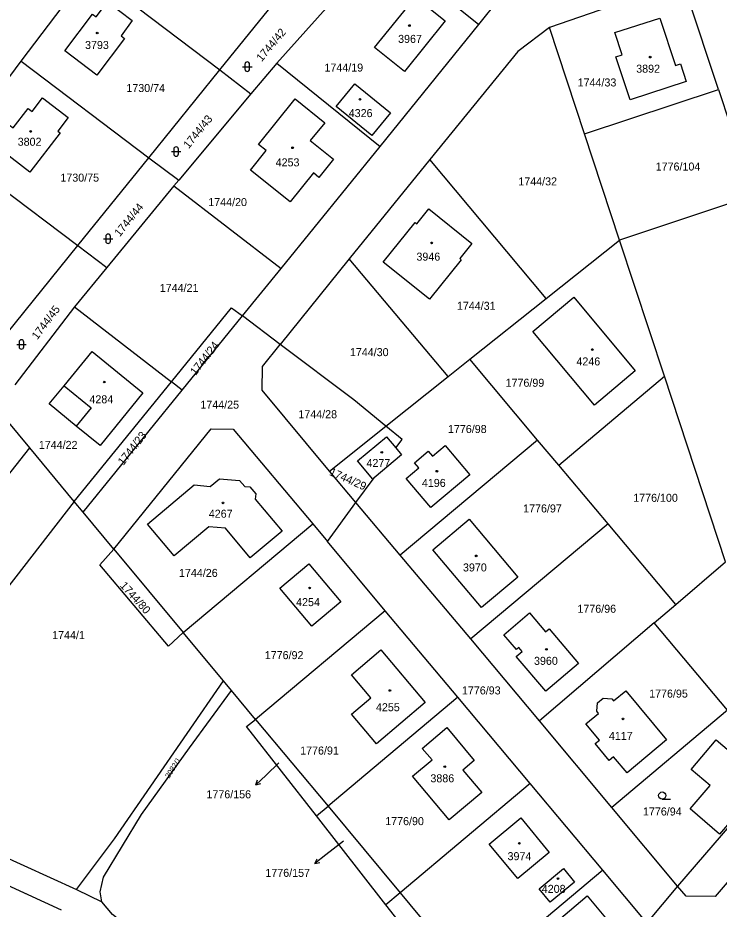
# Model space of a CAD drawing. Extents: x -679220 to -673243, y -1075091 to -1066557.
# Drawn here: x -677014 to -676865, y -1072590.3 to -1072401 of the extents above; entities that cross this region are included whole.
import ezdxf

# ---------------------------------------------------------------- set-up
doc = ezdxf.new("R2010")
doc.units = 0
for name, color, linetype in [('Hranice parcel', 7, 'Continuous'), ('Parcelní čísla', 7, 'Continuous'), ('Pop  PČ popisy', 7, 'Continuous'), ('Vnitřní kresba', 7, 'Continuous'), ('Značky budov', 7, 'Continuous'), ('Značky kultur', 7, 'Continuous')]:
    doc.layers.add(name, color=color, linetype=linetype)

msp = doc.modelspace()

# ---------------------------------------------------------------- linework, layer by layer
at = {"layer": 'Hranice parcel'}
for p, q in [((-676936.55, -1072385.82), (-676916.03, -1072402.47)), ((-677013.21, -1072410.27), (-676998.74, -1072391.12)), ((-676998.74, -1072391.12), (-676971, -1072412.08)), ((-676971, -1072412.08), (-676955.89, -1072393.41)), ((-676948.47, -1072399.01), (-676958.94, -1072410.64)), ((-676936.98, -1072428.37), (-676916.03, -1072402.47)), ((-676893.58, -1072425.69), (-676901.03, -1072403.13)), ((-677027.68, -1072429.42), (-677013.21, -1072410.27)), ((-677013.21, -1072410.27), (-676986.1, -1072430.75)), ((-676986.1, -1072430.75), (-676971, -1072412.08)), ((-676971, -1072412.08), (-676964.44, -1072417.17)), ((-676958.94, -1072410.64), (-676964.44, -1072417.17)), ((-676958.94, -1072410.64), (-676936.98, -1072428.37)), ((-676964.44, -1072417.17), (-676979.76, -1072435.5)), ((-676893.58, -1072425.69), (-676865.11, -1072416.25)), ((-676886.14, -1072448.25), (-676893.58, -1072425.69)), ((-676958.03, -1072454.3), (-676936.98, -1072428.37)), ((-677027.68, -1072429.42), (-677001.2, -1072449.42)), ((-677001.2, -1072449.42), (-676986.1, -1072430.75)), ((-676986.1, -1072430.75), (-676979.76, -1072435.5)), ((-676926.44, -1072431.16), (-676943.53, -1072452.25)), ((-676901.74, -1072460.64), (-676926.44, -1072431.16)), ((-676980.82, -1072436.75), (-676995.05, -1072454.05)), ((-676979.76, -1072435.5), (-676980.82, -1072436.75)), ((-676980.82, -1072436.75), (-676958.03, -1072454.3)), ((-676901.74, -1072460.64), (-676886.14, -1072448.25)), ((-676876.54, -1072477.15), (-676886.14, -1072448.25)), ((-677019.83, -1072472.45), (-677001.2, -1072449.42)), ((-677001.2, -1072449.42), (-676995.05, -1072454.05)), ((-676943.53, -1072452.25), (-676958.19, -1072470.4)), ((-676922.55, -1072477.22), (-676943.53, -1072452.25)), ((-676995.05, -1072454.05), (-677001.89, -1072462.45)), ((-676966.23, -1072464.36), (-676958.03, -1072454.3)), ((-676917.9, -1072473.51), (-676901.74, -1072460.64)), ((-677001.89, -1072462.45), (-677014.57, -1072478.97)), ((-677001.89, -1072462.45), (-676981.32, -1072478.34)), ((-676979.04, -1072480.1), (-676966.23, -1072464.36)), ((-676958.19, -1072470.4), (-676966.23, -1072464.36)), ((-676961.96, -1072475.06), (-676958.19, -1072470.4)), ((-676922.55, -1072477.22), (-676917.9, -1072473.51)), ((-676903.54, -1072490.7), (-676917.9, -1072473.51)), ((-677001.95, -1072503.72), (-676981.32, -1072478.34)), ((-676979.04, -1072480.1), (-676981.32, -1072478.34)), ((-676935.75, -1072487.75), (-676922.55, -1072477.22)), ((-676899.03, -1072496.01), (-676876.54, -1072477.15)), ((-676863.58, -1072516.59), (-676876.54, -1072477.15)), ((-677000.06, -1072506), (-676979.04, -1072480.1)), ((-677011.4, -1072492.35), (-677018.39, -1072483.95)), ((-676947.74, -1072497.31), (-676935.75, -1072487.75)), ((-676935.65, -1072490), (-676933.63, -1072492.39)), ((-676903.54, -1072490.7), (-676932.73, -1072515.13)), ((-676899.03, -1072496.01), (-676903.54, -1072490.7)), ((-677063.46, -1072557.99), (-677011.4, -1072492.35)), ((-677001.95, -1072503.72), (-677011.4, -1072492.35)), ((-676942.11, -1072504), (-676947.74, -1072497.31)), ((-676888.56, -1072508.51), (-676899.03, -1072496.01)), ((-676942.11, -1072504), (-676938.28, -1072498.75)), ((-676938.28, -1072498.75), (-676938.55, -1072498.98)), ((-677001.95, -1072503.72), (-677049.16, -1072564.49)), ((-677000.06, -1072506), (-677001.95, -1072503.72)), ((-676948.16, -1072512.28), (-676942.11, -1072504)), ((-676932.73, -1072515.13), (-676942.11, -1072504)), ((-676993.55, -1072513.87), (-677000.06, -1072506)), ((-676978.83, -1072531.58), (-676951.31, -1072508.5)), ((-676951.31, -1072508.5), (-676948.16, -1072512.28)), ((-676888.56, -1072508.51), (-676917.69, -1072532.9)), ((-676874.19, -1072525.66), (-676888.56, -1072508.51)), ((-676935.94, -1072526.95), (-676948.16, -1072512.28)), ((-676993.55, -1072513.87), (-676978.83, -1072531.58)), ((-676917.69, -1072532.9), (-676932.73, -1072515.13)), ((-676874.19, -1072525.66), (-676863.58, -1072516.59)), ((-676878.76, -1072529.49), (-676874.19, -1072525.66)), ((-676935.94, -1072526.95), (-676963.45, -1072550.02)), ((-676920.45, -1072545.27), (-676935.94, -1072526.95)), ((-676878.76, -1072529.49), (-676903.14, -1072550.36)), ((-676863.18, -1072548.07), (-676878.76, -1072529.49)), ((-676970.29, -1072541.82), (-676978.83, -1072531.58)), ((-676903.14, -1072550.36), (-676917.69, -1072532.9)), ((-676968.55, -1072543.9), (-676970.29, -1072541.82)), ((-676963.45, -1072550.02), (-676968.55, -1072543.9)), ((-676920.45, -1072545.27), (-676948.01, -1072568.43)), ((-676905.1, -1072563.63), (-676920.45, -1072545.27)), ((-676863.18, -1072548.07), (-676887.79, -1072568.76)), ((-676965.38, -1072551.53), (-676963.45, -1072550.02)), ((-676963.45, -1072550.02), (-676948.01, -1072568.43)), ((-676887.79, -1072568.76), (-676903.14, -1072550.36)), ((-676950.51, -1072570.53), (-676965.38, -1072551.53)), ((-676905.1, -1072563.63), (-676932.72, -1072586.85)), ((-676889.67, -1072582.03), (-676905.1, -1072563.63)), ((-677049.16, -1072564.49), (-677001.46, -1072586.15)), ((-676950.51, -1072570.53), (-676948.01, -1072568.43)), ((-676948.01, -1072568.43), (-676932.72, -1072586.85)), ((-676873.78, -1072585.43), (-676887.79, -1072568.76)), ((-676859.53, -1072568.86), (-676873.78, -1072585.43)), ((-676935.74, -1072589.39), (-676950.51, -1072570.53)), ((-676889.67, -1072582.03), (-676917.41, -1072605.32)), ((-676880.3, -1072593.22), (-676889.67, -1072582.03)), ((-677001.46, -1072586.15), (-676996.12, -1072588.79)), ((-676873.78, -1072585.43), (-676880.3, -1072593.22)), ((-676932.72, -1072586.85), (-676935.74, -1072589.39)), ((-676932.72, -1072586.85), (-676917.41, -1072605.32)), ((-676899.11, -1072592.68), (-676893, -1072587.47)), ((-676893, -1072587.47), (-676884.26, -1072597.96)), ((-676920.96, -1072608.27), (-676935.74, -1072589.39))]:
    msp.add_line(p, q, dxfattribs=at)
for points in [[(-676916.03, -1072402.47), (-676911.66, -1072396.99), (-676907.56, -1072394.23), (-676891.76, -1072389.1)], [(-676865.11, -1072416.25), (-676871.72, -1072396.17), (-676875.51, -1072394.24), (-676901.03, -1072403.13)], [(-676923.13, -1072401.7), (-676931.78, -1072412.45), (-676938.15, -1072407.32), (-676929.48, -1072396.56), (-676923.13, -1072401.7)], [(-677003.97, -1072408.09), (-676998.08, -1072400.28), (-676997.34, -1072400.82), (-676994.91, -1072397.66), (-676989.63, -1072401.63), (-676992.03, -1072404.84), (-676991.27, -1072405.43), (-676997.16, -1072413.21), (-677003.97, -1072408.09)], [(-676873.2, -1072410.8), (-676871.97, -1072414.56), (-676883.88, -1072418.47), (-676886.89, -1072409.32), (-676885.55, -1072408.87), (-676887.09, -1072404.19), (-676877.56, -1072401.1), (-676874.24, -1072411.14), (-676873.2, -1072410.8)], [(-676901.03, -1072403.13), (-676907.76, -1072408.23), (-676926.44, -1072431.16)], [(-676946.31, -1072419.89), (-676942.39, -1072415.08), (-676934.81, -1072421.2), (-676938.72, -1072426.02), (-676946.31, -1072419.89)], [(-676865.11, -1072416.25), (-676857.64, -1072438.81), (-676886.14, -1072448.25)], [(-677018.97, -1072428.02), (-677015.75, -1072423.84), (-677014.96, -1072424.44), (-677011.75, -1072420.27), (-677010.89, -1072420.93), (-677008.7, -1072418.05), (-677003.29, -1072422.23), (-677005.47, -1072425.12), (-677004.97, -1072425.5), (-677011.41, -1072433.85), (-677018.97, -1072428.02)], [(-676946.9, -1072431.06), (-676949.97, -1072434.92), (-676951.14, -1072433.96), (-676956.06, -1072440.14), (-676964.52, -1072433.37), (-676961.21, -1072429.24), (-676962.81, -1072427.96), (-676955.04, -1072418.27), (-676948.75, -1072423.33), (-676951.81, -1072427.12), (-676946.9, -1072431.06)], [(-676919.74, -1072452.43), (-676926.49, -1072460.82), (-676936.31, -1072452.91), (-676929.52, -1072444.51), (-676929.21, -1072444.8), (-676926.64, -1072441.62), (-676917.53, -1072449), (-676920.07, -1072452.16), (-676919.74, -1072452.43)], [(-676904.53, -1072467.63), (-676895.85, -1072460.4), (-676882.82, -1072476.03), (-676891.44, -1072483.28), (-676904.53, -1072467.63)], [(-676981.32, -1072478.34), (-676968.55, -1072462.62), (-676966.23, -1072464.36)], [(-676935.75, -1072487.75), (-676942.54, -1072482.15), (-676958.19, -1072470.4)], [(-676996.49, -1072491.85), (-677001.55, -1072487.73), (-677007.29, -1072483.05), (-677004.13, -1072479.17), (-676998.15, -1072471.9), (-676987.39, -1072480.67), (-676996.49, -1072491.85)], [(-676947.74, -1072497.31), (-676962.04, -1072480.14), (-676961.96, -1072475.06)], [(-676933.63, -1072492.39), (-676932.31, -1072490.58), (-676935.75, -1072487.75)], [(-676993.55, -1072513.87), (-676972.87, -1072488.34), (-676968.19, -1072488.36), (-676951.31, -1072508.5)], [(-676938.55, -1072498.98), (-676941.78, -1072495.15), (-676935.65, -1072490)], [(-676933.63, -1072492.39), (-676932.42, -1072493.82), (-676938.28, -1072498.75)], [(-676928.76, -1072496.61), (-676929.66, -1072495.54), (-676926.76, -1072493.06), (-676925.84, -1072494.12), (-676923.17, -1072491.88), (-676917.91, -1072498.1), (-676926.21, -1072505.03), (-676931.43, -1072498.86), (-676928.76, -1072496.61)], [(-676963.42, -1072502.11), (-676963.53, -1072503.25), (-676957.82, -1072510.06), (-676964.6, -1072515.73), (-676969.84, -1072509.45), (-676973.34, -1072509.15), (-676980.75, -1072515.32), (-676986.4, -1072508.54), (-676976.51, -1072500.25), (-676973.06, -1072500.55), (-676971.09, -1072498.94), (-676966.87, -1072499.3), (-676965.73, -1072500.58), (-676964.63, -1072500.65), (-676963.42, -1072502.11)], [(-676918.07, -1072507.53), (-676907.76, -1072519.8), (-676915.45, -1072526.28), (-676925.8, -1072514), (-676918.07, -1072507.53)], [(-676978.83, -1072531.58), (-676981.91, -1072534.5), (-676996.51, -1072517.23), (-676993.55, -1072513.87)], [(-676952.11, -1072516.96), (-676945.33, -1072525.06), (-676951.46, -1072530.23), (-676958.29, -1072522.13), (-676952.11, -1072516.96)], [(-676901.84, -1072531.42), (-676901.07, -1072530.77), (-676894.81, -1072538.15), (-676901.79, -1072544.05), (-676908.07, -1072536.66), (-676906.84, -1072535.62), (-676907.53, -1072534.79), (-676908.03, -1072535.2), (-676910.69, -1072532.06), (-676905.23, -1072527.43), (-676901.84, -1072531.42)], [(-676938.98, -1072545.45), (-676943.09, -1072540.58), (-676936.83, -1072535.27), (-676927.41, -1072546.47), (-676937.76, -1072555.2), (-676943.06, -1072548.9), (-676938.98, -1072545.45)], [(-677001.46, -1072586.15), (-676993.39, -1072575.36), (-676970.29, -1072541.82)], [(-676996.12, -1072588.79), (-676996.46, -1072586.67), (-676995.73, -1072583.55), (-676987.66, -1072570.19), (-676977.45, -1072556.03), (-676968.55, -1072543.9)], [(-676887.39, -1072558), (-676888.31, -1072558.76), (-676891.32, -1072555.17), (-676890.39, -1072554.42), (-676893.26, -1072550.97), (-676890.59, -1072548.74), (-676890.96, -1072548.3), (-676890.8, -1072546.5), (-676889.59, -1072545.52), (-676887.77, -1072545.66), (-676887.41, -1072546.1), (-676884.8, -1072543.93), (-676876.12, -1072554.37), (-676884.53, -1072561.4), (-676887.39, -1072558)], [(-676925.92, -1072558.58), (-676928.02, -1072556.18), (-676922.83, -1072551.77), (-676917, -1072558.74), (-676919.43, -1072560.8), (-676915.4, -1072565.55), (-676922.29, -1072571.38), (-676930.08, -1072562.08), (-676925.92, -1072558.58)], [(-676859.53, -1072568.86), (-676859.89, -1072568.55), (-676864.87, -1072574.4), (-676871.14, -1072569.04), (-676866.89, -1072564.06), (-676870.91, -1072560.63), (-676865.58, -1072554.33), (-676859.92, -1072559.2), (-676859.08, -1072558.22), (-676854.07, -1072562.51)], [(-676847.73, -1072566.56), (-676865.82, -1072587.66), (-676871.98, -1072587.57), (-676873.78, -1072585.43)], [(-677004.68, -1072590.55), (-677019.84, -1072583.59), (-677052.27, -1072568.5)], [(-676913.81, -1072576.52), (-676907.1, -1072570.96), (-676901.04, -1072578.28), (-676907.76, -1072583.84), (-676913.81, -1072576.52)], [(-676903.19, -1072585.99), (-676898.05, -1072581.7), (-676895.71, -1072584.56), (-676900.84, -1072588.82), (-676903.19, -1072585.99)], [(-676921.55, -1072642.56), (-676950.23, -1072623.95), (-676977.42, -1072604.43), (-676993.84, -1072591.45), (-676996.12, -1072588.79)]]:
    msp.add_lwpolyline(points, dxfattribs=at)
at = {"layer": 'Pop  PČ popisy'}
for p, q in [((-676958.47, -1072559.23), (-676961.22, -1072561.86)), ((-676961.22, -1072561.86), (-676963.38, -1072563.95)), ((-676963.38, -1072563.95), (-676963.01, -1072562.89)), ((-676963.38, -1072563.95), (-676962.31, -1072563.61)), ((-676944.78, -1072575.91), (-676948.5, -1072578.78)), ((-676948.5, -1072578.78), (-676950.86, -1072580.63)), ((-676950.86, -1072580.63), (-676950.38, -1072579.62)), ((-676950.86, -1072580.63), (-676949.77, -1072580.41))]:
    msp.add_line(p, q, dxfattribs=at)
at = {"layer": 'Vnitřní kresba'}
for p, q in [((-677004.13, -1072479.17), (-676998.39, -1072483.85)), ((-676998.39, -1072483.85), (-677001.55, -1072487.73))]:
    msp.add_line(p, q, dxfattribs=at)
at = {"layer": 'Značky budov'}
for centre in [(-676930.75, -1072402.68), (-676997.08, -1072404.27), (-676879.6, -1072409.39), (-676941.26, -1072418.35), (-677011.21, -1072425.18), (-676955.58, -1072428.64), (-676926.05, -1072448.84), (-676891.91, -1072471.48), (-676995.59, -1072478.39), (-676936.63, -1072493.3), (-676924.93, -1072497.32), (-676970.35, -1072504.05), (-676916.58, -1072515.3), (-676951.96, -1072522.11), (-676901.64, -1072535.16), (-676934.91, -1072543.89), (-676885.38, -1072549.92), (-676923.24, -1072560.05), (-676907.4, -1072576.34), (-676899.19, -1072583.82)]:
    msp.add_circle(centre, 0.175, dxfattribs=at)
at = {"layer": 'Značky kultur'}
for p, q in [((-676966.2, -1072411.42), (-676964.2, -1072411.42)), ((-676965.7, -1072410.92), (-676965.7, -1072411.92)), ((-676964.7, -1072411.92), (-676964.7, -1072410.92)), ((-676980.82, -1072428.95), (-676980.82, -1072429.95)), ((-676979.82, -1072429.95), (-676979.82, -1072428.95)), ((-676981.32, -1072429.45), (-676979.32, -1072429.45)), ((-676995.78, -1072447.96), (-676993.78, -1072447.96)), ((-676995.28, -1072447.46), (-676995.28, -1072448.46)), ((-676994.28, -1072448.46), (-676994.28, -1072447.46)), ((-677014.19, -1072470.41), (-677012.19, -1072470.41)), ((-677013.69, -1072469.91), (-677013.69, -1072470.91)), ((-677012.69, -1072470.91), (-677012.69, -1072469.91)), ((-676877.06, -1072566.94), (-676875.31, -1072566.94))]:
    msp.add_line(p, q, dxfattribs=at)
msp.add_circle((-676877.06, -1072566.19), 0.75, dxfattribs=at)
for centre, start, end in [((-676965.2, -1072410.92), 0, 180), ((-676965.2, -1072411.92), 180, 359.9879), ((-676980.32, -1072428.95), 0, 180), ((-676980.32, -1072429.95), 180, 359.9879), ((-676994.78, -1072447.46), 0, 180), ((-676994.78, -1072448.46), 180, 359.9879), ((-677013.19, -1072469.91), 0, 180), ((-677013.19, -1072470.91), 180, 359.9879)]:
    msp.add_arc(centre, 0.5, start, end, dxfattribs=at)

# ---------------------------------------------------------------- texts
at = {"layer": 'Parcelní čísla'}
for s, height, rotation, p in [('1744/42', 1.7, 50, (-676962.14, -1072410.47)), ('1744/43', 1.7, 51, (-676977.64, -1072428.95)), ('1744/44', 1.7, 51, (-676992.29, -1072447.65)), ('1744/45', 1.7, 53, (-677009.81, -1072469.51)), ('1744/24', 1.7, 52, (-676976.17, -1072477.09)), ('1744/23', 1.7, 52, (-676991.53, -1072496.21)), ('1744/29', 1.7, 336, (-676947.9, -1072498.09)), ('1744/80', 1.7, 312, (-676992.35, -1072521.69)), ('2082/1', 1.14, 58, (-676981.79, -1072562.64))]:
    msp.add_text(s, height=height, rotation=rotation, dxfattribs=at).set_placement(p)
for s, p in [('3967', (-676933.16, -1072406.37)), ('3793', (-676999.67, -1072407.66)), ('1744/19', (-676948.81, -1072412.46)), ('3892', (-676882.58, -1072412.7)), ('1744/33', (-676895.02, -1072415.62)), ('1730/74', (-676990.89, -1072416.8)), ('4326', (-676943.65, -1072422.13)), ('3802', (-677013.98, -1072428.21)), ('4253', (-676959.18, -1072432.59)), ('1776/104', (-676878.44, -1072433.48)), ('1730/75', (-677004.91, -1072435.83)), ('1744/32', (-676907.62, -1072436.63)), ('1744/20', (-676973.49, -1072441.02)), ('3946', (-676929.27, -1072452.61)), ('1744/21', (-676983.79, -1072459.25)), ('1744/31', (-676920.67, -1072463.05)), ('1744/30', (-676943.4, -1072472.89)), ('4246', (-676895.28, -1072474.86)), ('1776/99', (-676910.33, -1072479.39)), ('4284', (-676998.74, -1072482.9)), ('1744/25', (-676975.17, -1072484.04)), ('1744/28', (-676954.35, -1072486.07)), ('1776/98', (-676922.57, -1072489.21)), ('1744/22', (-677009.49, -1072492.59)), ('4277', (-676939.88, -1072496.43)), ('4196', (-676928.11, -1072500.66)), ('1776/100', (-676883.21, -1072503.82)), ('1776/97', (-676906.6, -1072506.08)), ('4267', (-676973.38, -1072507.2)), ('1744/26', (-676979.71, -1072519.77)), ('3970', (-676919.38, -1072518.61)), ('4254', (-676954.83, -1072525.97)), ('1776/96', (-676895.07, -1072527.38)), ('1744/1', (-677006.66, -1072532.97)), ('1776/92', (-676961.49, -1072537.23)), ('3960', (-676904.29, -1072538.44)), ('1776/93', (-676919.6, -1072544.72)), ('1776/95', (-676879.83, -1072545.4)), ('4255', (-676937.87, -1072548.29)), ('4117', (-676888.38, -1072554.37)), ('1776/91', (-676953.97, -1072557.49)), ('3886', (-676926.3, -1072563.38)), ('1776/156', (-676973.88, -1072566.78)), ('1776/94', (-676881.14, -1072570.43)), ('1776/90', (-676935.9, -1072572.48)), ('3974', (-676909.91, -1072579.92)), ('1776/157', (-676961.36, -1072583.46)), ('4208', (-676902.64, -1072586.86))]:
    msp.add_text(s, height=1.7, dxfattribs=at).set_placement(p)

doc.saveas('drawing.dxf')
